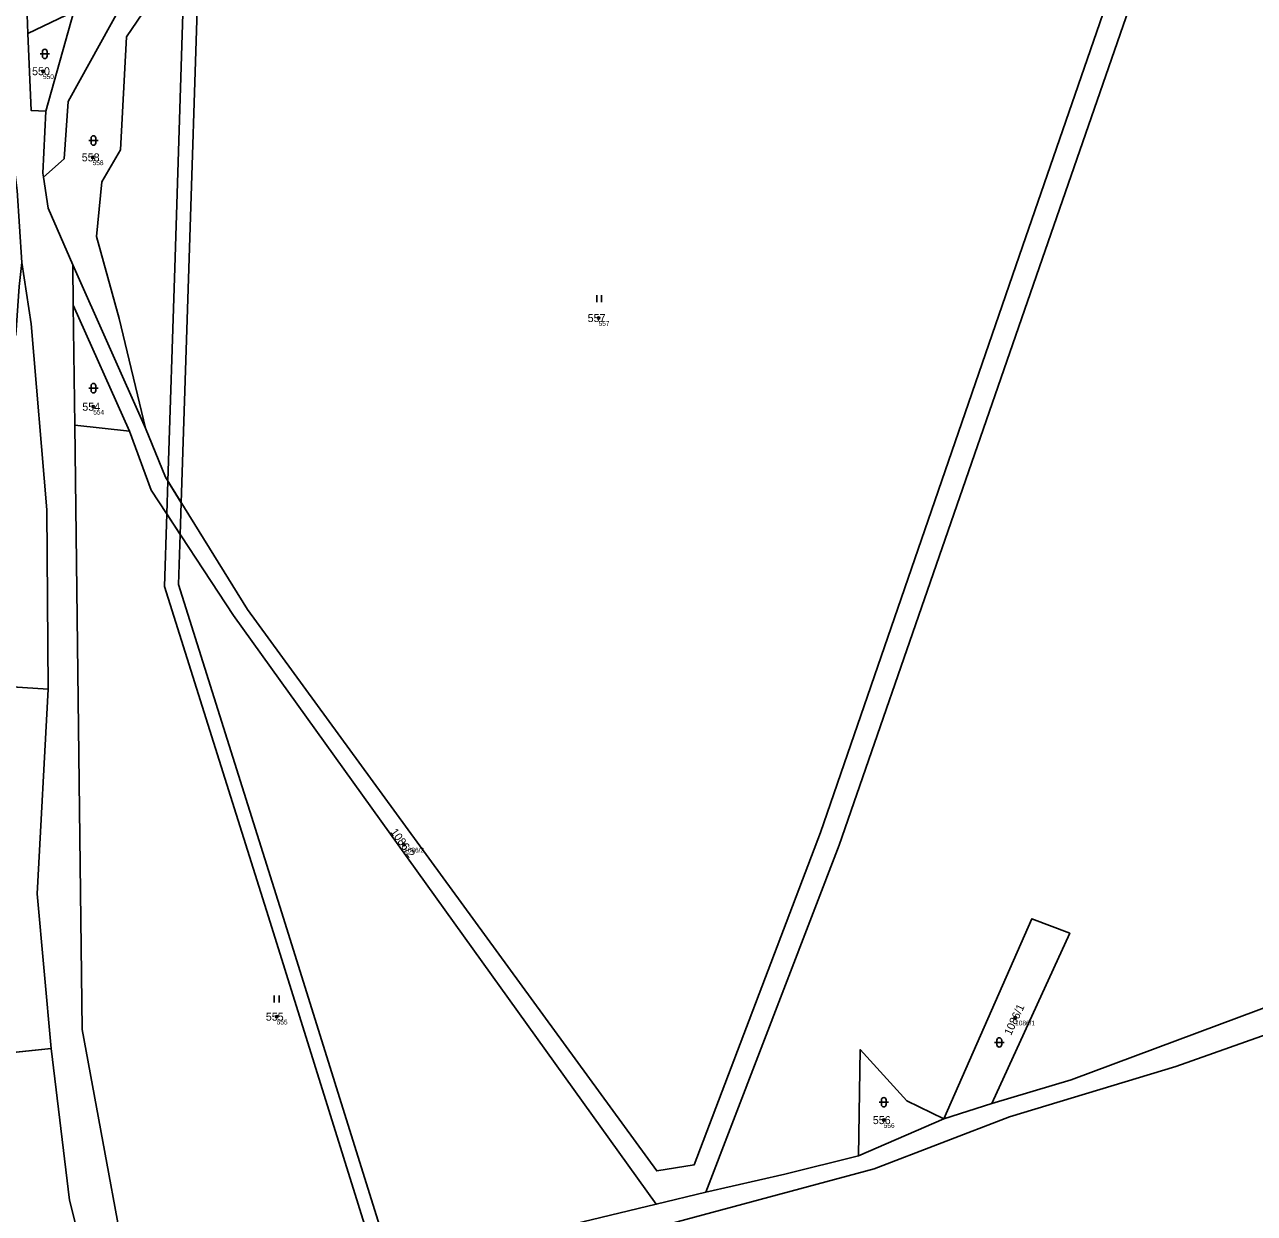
# Model space of a CAD drawing. Extents: x -554500 to -548272, y -1079733 to -1073730.
# Drawn here: x -553550.7 to -553289.5, y -1076230.3 to -1075977.7 of the extents above; entities that cross this region are included whole.
import ezdxf

# ---------------------------------------------------------------- set-up
doc = ezdxf.new("R2010")
doc.units = 0
for name, color, linetype in [('Definiční body', 7, 'Continuous'), ('Hranice parcel', 7, 'Continuous'), ('Parcelní čísla', 7, 'Continuous'), ('Polygon parcely', 7, 'Continuous'), ('Věcná břemena k části', 7, 'Continuous'), ('Značky kultur', 7, 'Continuous')]:
    doc.layers.add(name, color=color, linetype=linetype)

msp = doc.modelspace()

# ---------------------------------------------------------------- linework, layer by layer
at = {"layer": 'Definiční body'}
for centre in [(-553546.77, -1075987.57994), (-553536.22, -1076005.87994), (-553428.77, -1076040.01994), (-553536.1, -1076058.86994), (-553470.07, -1076151.90994), (-553497.13, -1076188.45994), (-553340.3, -1076188.64994), (-553368.21, -1076210.42994)]:
    msp.add_circle(centre, 0.25, dxfattribs=at)
at = {"layer": 'Hranice parcel'}
for p, q in [((-553549.97, -1075979.57), (-553550.13, -1075975.63)), ((-553540.38, -1076037.29), (-553540.45, -1076028.75)), ((-553540.45, -1076028.75), (-553525.03, -1076063.4)), ((-553528.4, -1076064.05), (-553540.38, -1076037.29)), ((-553540.38, -1076037.29), (-553540.03, -1076062.78)), ((-553540.03, -1076062.78), (-553528.4, -1076064.05)), ((-553566.58, -1076117.53), (-553545.66, -1076118.89)), ((-553573.9, -1076198.27), (-553545.07, -1076195.19)), ((-553345.23, -1076206.92), (-553355.43, -1076210.16)), ((-553373.61, -1076218.02), (-553355.43, -1076210.16)), ((-553406.03, -1076225.78), (-553416.52, -1076228.3))]:
    msp.add_line(p, q, dxfattribs=at)
for points in [[(-553289.77, -1075898.12), (-553333.95, -1076025.64), (-553377.65, -1076151.99), (-553406.03, -1076225.78)], [(-553525.03, -1076063.4), (-553520.78, -1076073.84), (-553503.31, -1076101.93), (-553416.41, -1076221.24), (-553408.46, -1076219.93), (-553381.66, -1076149.33), (-553338.72, -1076024.82), (-553296.03, -1075901.24)], [(-553484.64, -1075952.35), (-553491.42, -1075952.82), (-553518.47, -1075960.41), (-553525.68, -1075965.52), (-553541.43, -1075993.99), (-553542.29, -1076006.16), (-553546.66, -1076010.11)], [(-553484.64, -1075952.35), (-553488.8, -1075963.74), (-553521.86, -1075972.03), (-553524.53, -1075973.64), (-553529.02, -1075980.29), (-553530.33, -1076004.29), (-553534.25, -1076011.1), (-553535.39, -1076022.67), (-553530.6, -1076040.13), (-553525.03, -1076063.4)], [(-553546.2, -1075996.04), (-553540.24, -1075974.87), (-553549.97, -1075979.57)], [(-553549.97, -1075979.57), (-553549.26, -1075995.93), (-553546.2, -1075996.04)], [(-553546.66, -1076010.11), (-553546.79, -1076009.24), (-553546.2, -1075996.04)], [(-553546.66, -1076010.11), (-553545.66, -1076016.64), (-553540.45, -1076028.75)], [(-553545.66, -1076118.89), (-553545.99, -1076080.74), (-553549.31, -1076041.25), (-553551.24, -1076028.23)], [(-553540.03, -1076062.78), (-553538.46, -1076191.18), (-553525.82, -1076259.86)], [(-553416.52, -1076228.3), (-553506.31, -1076103.2), (-553523.83, -1076076.58), (-553528.4, -1076064.05)], [(-553545.07, -1076195.19), (-553548.04, -1076162.34), (-553545.66, -1076118.89)], [(-553192.34, -1076153.61), (-553234.53, -1076172.39), (-553265.17, -1076184.53), (-553306.2, -1076199.03), (-553341.51, -1076209.72), (-553370.28, -1076220.81), (-553470.81, -1076247.85), (-553481.88, -1076252.19)], [(-553345.23, -1076206.92), (-553328.38, -1076201.9), (-553261.77, -1076176.99), (-553235.43, -1076166.44), (-553224.5, -1076161.33)], [(-553355.43, -1076210.16), (-553336.77, -1076167.66), (-553328.71, -1076170.75), (-553345.23, -1076206.92)], [(-553545.07, -1076195.19), (-553541.12, -1076227.45), (-553532.22, -1076262.89)], [(-553355.43, -1076210.16), (-553363.31, -1076206.31), (-553373.19, -1076195.46), (-553373.61, -1076218.02)], [(-553406.03, -1076225.78), (-553389.24, -1076221.89), (-553373.61, -1076218.02)], [(-553523.26, -1076259.26), (-553493.27, -1076252.2), (-553447.72, -1076235.81), (-553416.52, -1076228.3)]]:
    msp.add_lwpolyline(points, dxfattribs=at)
at = {"layer": 'Polygon parcely'}
for points in [[(-553289.77, -1075898.12), (-553333.95, -1076025.64), (-553377.65, -1076151.99), (-553406.03, -1076225.78), (-553389.24, -1076221.89), (-553373.61, -1076218.02), (-553373.19, -1076195.46), (-553363.31, -1076206.31), (-553355.43, -1076210.16), (-553336.77, -1076167.66), (-553328.71, -1076170.75), (-553345.23, -1076206.92), (-553328.38, -1076201.9), (-553261.77, -1076176.99), (-553235.43, -1076166.44), (-553224.5, -1076161.33), (-553219.35, -1076056.25), (-553214.2, -1075952.76), (-553231.25, -1075955.35), (-553260.09, -1075934.07), (-553272.06, -1075908.84), (-553280.31, -1075893.19)], [(-553289.77, -1075898.12), (-553296.03, -1075901.24), (-553338.72, -1076024.82), (-553381.66, -1076149.33), (-553408.46, -1076219.93), (-553416.41, -1076221.24), (-553503.31, -1076101.93), (-553520.78, -1076073.84), (-553525.03, -1076063.4), (-553540.45, -1076028.75), (-553540.38, -1076037.29), (-553528.4, -1076064.05), (-553523.83, -1076076.58), (-553506.31, -1076103.2), (-553416.52, -1076228.3), (-553406.03, -1076225.78), (-553377.65, -1076151.99), (-553333.95, -1076025.64)], [(-553347.41, -1075918.01), (-553422.33, -1075935.82), (-553449.31, -1075944.74), (-553484.64, -1075952.35), (-553488.8, -1075963.74), (-553521.86, -1075972.03), (-553524.53, -1075973.64), (-553529.02, -1075980.29), (-553530.33, -1076004.29), (-553534.25, -1076011.1), (-553535.39, -1076022.67), (-553530.6, -1076040.13), (-553525.03, -1076063.4), (-553520.78, -1076073.84), (-553503.31, -1076101.93), (-553416.41, -1076221.24), (-553408.46, -1076219.93), (-553381.66, -1076149.33), (-553338.72, -1076024.82), (-553296.03, -1075901.24), (-553310.35, -1075907.74), (-553338.47, -1075914.11)], [(-553541.43, -1075993.99), (-553542.29, -1076006.16), (-553546.66, -1076010.11), (-553545.66, -1076016.64), (-553540.45, -1076028.75), (-553525.03, -1076063.4), (-553530.6, -1076040.13), (-553535.39, -1076022.67), (-553534.25, -1076011.1), (-553530.33, -1076004.29), (-553529.02, -1075980.29), (-553524.53, -1075973.64), (-553521.86, -1075972.03), (-553488.8, -1075963.74), (-553484.64, -1075952.35), (-553491.42, -1075952.82), (-553518.47, -1075960.41), (-553525.68, -1075965.52)], [(-553549.26, -1075995.93), (-553546.2, -1075996.04), (-553540.24, -1075974.87), (-553549.97, -1075979.57)], [(-553570.89, -1076097.78), (-553568.94, -1076097.8), (-553566.58, -1076117.53), (-553545.66, -1076118.89), (-553545.99, -1076080.74), (-553549.31, -1076041.25), (-553551.24, -1076028.23), (-553551.86, -1076033.33), (-553552.52, -1076043.61), (-553580.76, -1076041.79), (-553581.51, -1076064.9), (-553578.34, -1076064.98), (-553577.74, -1076050.62), (-553573.06, -1076050.46)], [(-553540.38, -1076037.29), (-553540.03, -1076062.78), (-553528.4, -1076064.05)], [(-553447.72, -1076235.81), (-553416.52, -1076228.3), (-553506.31, -1076103.2), (-553523.83, -1076076.58), (-553528.4, -1076064.05), (-553540.03, -1076062.78), (-553538.46, -1076191.18), (-553525.82, -1076259.86), (-553523.26, -1076259.26), (-553493.27, -1076252.2)], [(-553573.9, -1076198.27), (-553545.07, -1076195.19), (-553548.04, -1076162.34), (-553545.66, -1076118.89), (-553566.58, -1076117.53), (-553574.31, -1076116.99), (-553576.15, -1076136.26)], [(-553345.23, -1076206.92), (-553328.71, -1076170.75), (-553336.77, -1076167.66), (-553355.43, -1076210.16)], [(-553545.07, -1076195.19), (-553573.9, -1076198.27), (-553572.76, -1076230.14), (-553563.63, -1076270.79), (-553558.27, -1076269.3), (-553539.78, -1076265.45), (-553532.22, -1076262.89), (-553541.12, -1076227.45)], [(-553363.31, -1076206.31), (-553373.19, -1076195.46), (-553373.61, -1076218.02), (-553355.43, -1076210.16)]]:
    msp.add_lwpolyline(points, close=True, dxfattribs=at)
for points in [[(-553558.75, -1075962.49), (-553556.64, -1075979.11), (-553552.27, -1076012.92), (-553551.24, -1076028.23), (-553549.31, -1076041.25), (-553545.99, -1076080.74), (-553545.66, -1076118.89), (-553548.04, -1076162.34), (-553545.07, -1076195.19), (-553541.12, -1076227.45), (-553532.22, -1076262.89), (-553526.59, -1076286.28), (-553515.73, -1076315.86), (-553517.78, -1076348.04), (-553513.1, -1076368.85), (-553513, -1076369.32), (-553505.39, -1076372.56), (-553496.78, -1076380.19), (-553489.13, -1076396.51), (-553486.95, -1076405.57), (-553481.77, -1076427.04)], [(-553550.13, -1075975.63), (-553549.97, -1075979.57), (-553540.24, -1075974.87), (-553546.2, -1075996.04), (-553546.79, -1076009.24), (-553546.66, -1076010.11), (-553542.29, -1076006.16), (-553541.43, -1075993.99), (-553525.68, -1075965.52)], [(-553473.83, -1076425.13), (-553486.73, -1076383.91), (-553488.43, -1076380.02), (-553496.6, -1076372.46), (-553500.07, -1076369.25), (-553504.05, -1076362.31), (-553506.82, -1076358.3), (-553510.73, -1076345.52), (-553509.93, -1076336.3), (-553509.02, -1076314.96), (-553519.67, -1076285.69), (-553525.82, -1076259.86), (-553538.46, -1076191.18), (-553540.03, -1076062.78), (-553540.38, -1076037.29), (-553540.45, -1076028.75), (-553545.66, -1076016.64), (-553546.66, -1076010.11), (-553546.79, -1076009.24), (-553546.2, -1075996.04), (-553549.26, -1075995.93), (-553549.97, -1075979.57), (-553550.13, -1075975.63)], [(-553261.77, -1076176.99), (-553328.38, -1076201.9), (-553345.23, -1076206.92), (-553355.43, -1076210.16), (-553373.61, -1076218.02), (-553389.24, -1076221.89), (-553406.03, -1076225.78), (-553416.52, -1076228.3), (-553447.72, -1076235.81), (-553493.27, -1076252.2), (-553523.26, -1076259.26), (-553522.48, -1076263.07), (-553488.13, -1076255.08), (-553481.88, -1076252.19), (-553470.81, -1076247.85), (-553370.28, -1076220.81), (-553341.51, -1076209.72), (-553306.2, -1076199.03), (-553265.17, -1076184.53)], [(-553265.17, -1076184.53), (-553306.2, -1076199.03), (-553341.51, -1076209.72), (-553370.28, -1076220.81), (-553470.81, -1076247.85), (-553481.88, -1076252.19), (-553485.71, -1076271.7), (-553486.59, -1076309.43), (-553480, -1076337.85), (-553474.64, -1076350.25), (-553465.35, -1076351.76), (-553452.78, -1076349.7), (-553453.97, -1076345.27), (-553442.81, -1076342.26), (-553442.35, -1076343.97), (-553440.02, -1076341.73), (-553429.08, -1076342.46), (-553400.83, -1076331.52), (-553313.75, -1076308.26), (-553295.84, -1076305.09), (-553270.78, -1076295.45)]]:
    msp.add_lwpolyline(points, dxfattribs=at)
at = {"layer": 'Věcná břemena k části'}
for points in [[(-553520.26, -1076074.67), (-553517.41, -1076079.26), (-553515.77, -1076029.46), (-553513.91, -1075970.04), (-553516.93, -1075970.79), (-553518.77, -1076029.36)], [(-553520.49, -1076081.65), (-553517.63, -1076086), (-553517.41, -1076079.26), (-553520.26, -1076074.67)], [(-553474.48, -1076245.44), (-553471.65, -1076244.42), (-553473.87, -1076237.36), (-553495.7, -1076167.5), (-553517.98, -1076096.61), (-553517.63, -1076086), (-553520.49, -1076081.65), (-553521, -1076097.03), (-553498.56, -1076168.4), (-553476.73, -1076238.26)]]:
    msp.add_lwpolyline(points, close=True, dxfattribs=at)
at = {"layer": 'Značky kultur'}
for p, q in [((-553547.391, -1075983.911), (-553545.389, -1075983.911)), ((-553546.891, -1075983.411), (-553546.891, -1075984.412)), ((-553545.889, -1075984.412), (-553545.889, -1075983.411)), ((-553537.071, -1076002.301), (-553535.069, -1076002.301)), ((-553536.571, -1076001.801), (-553536.571, -1076002.802)), ((-553535.569, -1076002.802), (-553535.569, -1076001.801)), ((-553429.171, -1076036.63), (-553429.171, -1076035.13)), ((-553428.17, -1076036.63), (-553428.17, -1076035.13)), ((-553537.061, -1076054.921), (-553535.059, -1076054.921)), ((-553536.561, -1076054.421), (-553536.561, -1076055.422)), ((-553535.559, -1076055.422), (-553535.559, -1076054.421)), ((-553497.651, -1076185.47), (-553497.651, -1076183.97)), ((-553496.65, -1076185.47), (-553496.65, -1076183.97)), ((-553344.671, -1076193.921), (-553342.669, -1076193.921)), ((-553344.171, -1076193.421), (-553344.171, -1076194.422)), ((-553343.169, -1076194.422), (-553343.169, -1076193.421)), ((-553369.211, -1076206.641), (-553367.209, -1076206.641)), ((-553368.711, -1076206.141), (-553368.711, -1076207.142)), ((-553367.709, -1076207.142), (-553367.709, -1076206.141))]:
    msp.add_line(p, q, dxfattribs=at)
for centre, start, end in [((-553546.39, -1075983.4109), 0, 180), ((-553546.39, -1075984.4109), 180, 359.9878861), ((-553536.07, -1076001.8009), 0, 180), ((-553536.07, -1076002.8009), 180, 359.9878861), ((-553536.06, -1076054.4209), 0, 180), ((-553536.06, -1076055.4209), 180, 359.9878861), ((-553343.67, -1076193.4209), 0, 180), ((-553343.67, -1076194.4209), 180, 359.9878861), ((-553368.21, -1076206.1409), 0, 180), ((-553368.21, -1076207.1409), 180, 359.9878861)]:
    msp.add_arc(centre, 0.5, start, end, dxfattribs=at)

# ---------------------------------------------------------------- texts
at = {"layer": 'Definiční body'}
for s, p in [('550', (-553546.77, -1075989.236)), ('558', (-553536.22, -1076007.536)), ('557', (-553428.77, -1076041.676)), ('554', (-553536.1, -1076060.526)), ('1086/2', (-553470.07, -1076153.566)), ('555', (-553497.13, -1076190.116)), ('1086/1', (-553340.3, -1076190.306)), ('556', (-553368.21, -1076212.086))]:
    msp.add_text(s, height=0.999996, dxfattribs=at).set_placement(p)
at = {"layer": 'Parcelní čísla'}
for s, p in [('550', (-553549.095, -1075988.43)), ('558', (-553538.545, -1076006.73)), ('557', (-553431.095, -1076040.87)), ('554', (-553538.425, -1076059.72)), ('555', (-553499.455, -1076189.31)), ('556', (-553370.535, -1076211.28))]:
    msp.add_text(s, height=1.699998, dxfattribs=at).set_placement(p)
for s, rotation, p in [('1086/2', 306, (-553473.078, -1076149.215)), ('1086/1', 65, (-553341.197, -1076192.587))]:
    msp.add_text(s, height=1.699998, rotation=rotation, dxfattribs=at).set_placement(p)

doc.saveas('drawing.dxf')
